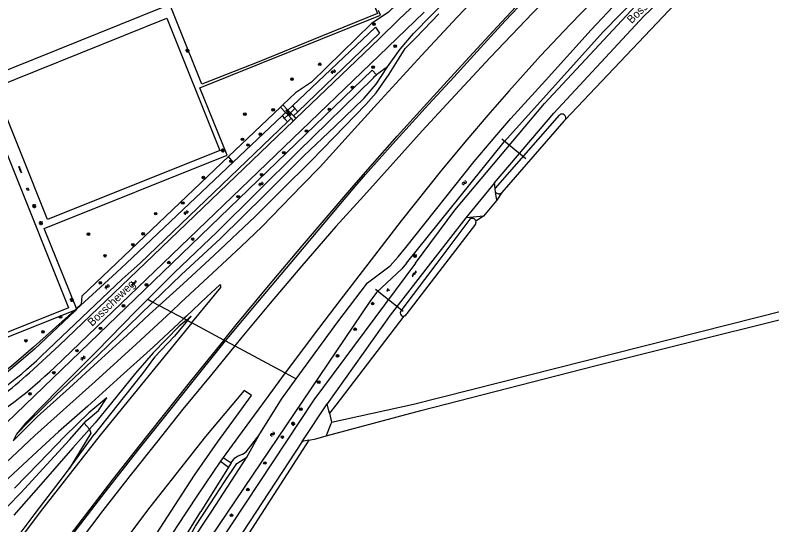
# Model space of a CAD drawing. Extents: x 137999 to 141000, y 397500 to 400501.
# Drawn here: x 138446.7 to 138683.2, y 398918.2 to 399077.5 of the extents above; entities that cross this region are included whole.
import ezdxf

# ---------------------------------------------------------------- set-up
doc = ezdxf.new("R2010")
doc.units = 0
for name, color, linetype in [('gg-afsc-hekwerk', 7, 'Continuous'), ('gg-anno-openbare ruimte label', 7, 'Continuous'), ('gg-knt-BGT kruinlijn', 7, 'Continuous'), ('gg-knt-verharding', 7, 'Continuous'), ('gg-kntw-bovenkant insteek waterloop', 7, 'Continuous'), ('gg-kwrk-duiker nz buis', 7, 'Continuous'), ('gt-grn-groengrens', 7, 'Continuous'), ('gt-symb-boom', 7, 'Continuous'), ('gt-symb-gesloten verharding', 7, 'Continuous'), ('gt-symb-groenvak', 7, 'Continuous'), ('gt-symb-kolk center center', 7, 'Continuous'), ('gt-symb-lichtmast', 7, 'Continuous'), ('gt-symb-tegel verharding', 7, 'Continuous'), ('gt-symb-watersymbool', 7, 'Continuous'), ('gx-grn-maaiveld', 7, 'Continuous')]:
    doc.layers.add(name, color=color, linetype=linetype)

# ---------------------------------------------------------------- blocks, each defined once
blk = doc.blocks.new('gt0-BOOM')
at = {"layer": 'gt-symb-boom'}
for radius in [0.4, 0.2]:
    blk.add_circle((0, 0), radius, dxfattribs=at)
blk = doc.blocks.new('gt0-WA')
at = {"layer": 'gt-symb-watersymbool'}
for centre, start, end in [((-0.32, 0.02), 28.0725, 151.9275), ((0.43, 0.42), 208.0725, 331.9275), ((-0.32, -0.43), 28.0725, 151.9275), ((0.43, -0.03), 208.0725, 331.9275)]:
    blk.add_arc(centre, 0.425, start, end, dxfattribs=at)
blk = doc.blocks.new('gt0-TEG1')
at = {"layer": 'gt-symb-tegel verharding'}
for p, q in [((-1.13, 0), (1.12, 0)), ((-0.9, -0.25), (-0.9, 0.25)), ((-0.45, -0.25), (-0.45, 0.25)), ((0, -0.25), (0, 0.25)), ((0.45, -0.25), (0.45, 0.25)), ((0.9, -0.25), (0.9, 0.25))]:
    blk.add_line(p, q, dxfattribs=at)
blk = doc.blocks.new('gt0-KOLKCC')
at = {"layer": 'gt-symb-kolk center center'}
blk.add_lwpolyline([(-0.38, 0.2), (0.37, 0.2), (0.37, -0.2), (-0.38, -0.2)], close=True, dxfattribs=at)
blk = doc.blocks.new('gt0-LMAST')
at = {"layer": 'gt-symb-lichtmast'}
for p, q in [((-0.18, 0.17), (-0.45, 0.44)), ((0, 0.25), (0, 0.62)), ((0.17, 0.17), (0.44, 0.44)), ((-0.25, 0), (-0.63, 0)), ((-0.18, -0.18), (-0.45, -0.45)), ((0, -0.25), (0, -0.63)), ((0.44, -0.45), (0.17, -0.18)), ((0.25, 0), (0.62, 0))]:
    blk.add_line(p, q, dxfattribs=at)
blk.add_circle((0, 0), 0.25, dxfattribs=at)
blk = doc.blocks.new('gt0-GESVH1')
at = {"layer": 'gt-symb-gesloten verharding'}
for p, q in [((-0.99, -0.26), (0.01, 0.24)), ((0.01, -0.26), (-0.99, 0.24)), ((0.01, 0.24), (1.01, -0.26)), ((1.01, 0.24), (0.01, -0.26))]:
    blk.add_line(p, q, dxfattribs=at)
blk = doc.blocks.new('gt0-GRVAK')
at = {"layer": 'gt-symb-groenvak'}
for p, q in [((-0.11, 0.19), (-0.23, 0.24)), ((-0.18, 0.15), (0.09, 0.15)), ((-0.09, 0.21), (-0.16, 0.32)), ((-0.05, 0.21), (-0.05, 0.39)), ((0, 0.21), (0.06, 0.32)), ((0.02, 0.19), (0.13, 0.24)), ((0.26, -0.05), (0.2, 0.06)), ((0.31, -0.05), (0.31, 0.13)), ((0.35, -0.05), (0.41, 0.06)), ((-0.24, -0.23), (-0.36, -0.18)), ((-0.32, -0.26), (-0.05, -0.26)), ((-0.23, -0.21), (-0.29, -0.09)), ((-0.18, -0.2), (-0.18, -0.02)), ((-0.14, -0.21), (-0.07, -0.09)), ((-0.12, -0.23), (0, -0.18)), ((0.24, -0.07), (0.12, -0.02)), ((0.17, -0.11), (0.44, -0.11)), ((0.37, -0.07), (0.49, -0.02))]:
    blk.add_line(p, q, dxfattribs=at)

msp = doc.modelspace()

# ---------------------------------------------------------------- linework, layer by layer
at = {"layer": 'gg-afsc-hekwerk'}
for p, q in [((138542.24, 399070.77), (138522.87, 399062.86)), ((138530.38, 399049.44), (138529.63, 399048.73)), ((138529.63, 399048.73), (138513.37, 399033.27)), ((138465.86, 398985.77), (138465.36, 398985.32))]:
    msp.add_line(p, q, dxfattribs=at)
for points in [[(138565.97, 399080.94), (138563.3, 399078.28), (138558.06, 399074.85), (138539.36, 399056.53), (138534.35, 399053.22), (138530.38, 399049.44)], [(138513.37, 399033.27), (138467.54, 398989.69), (138467.35, 398987.11), (138465.86, 398985.77)], [(138465.36, 398985.32), (138452.45, 398973.74), (138446.23, 398968.34), (138439.94, 398963.29), (138424.42, 398953.33), (138421.32, 398953.92), (138412.36, 398949.22)]]:
    msp.add_lwpolyline(points, dxfattribs=at)
at = {"layer": 'gg-knt-BGT kruinlijn'}
for p, q in [((138572.03, 399070.45), (138579.08, 399077.9)), ((138568.61, 399067), (138572.03, 399070.45)), ((138566.68, 399063.99), (138568.61, 399067)), ((138563.55, 399059.01), (138566.68, 399063.99)), ((138559.52, 399053.2), (138563.55, 399059.01)), ((138556.35, 399049.55), (138559.52, 399053.2)), ((138546.32, 399039.24), (138556.35, 399049.55)), ((138539.24, 399031.96), (138546.32, 399039.24)), ((138529.89, 399022.69), (138539.24, 399031.96)), ((138521.72, 399014.56), (138529.89, 399022.69)), ((138508.92, 399002.44), (138521.72, 399014.56)), ((138499.23, 398993.49), (138508.92, 399002.44)), ((138491.76, 398986.75), (138499.23, 398993.49)), ((138491.76, 398986.75), (138488.68, 398983.98)), ((138488.68, 398983.98), (138481.69, 398977.42)), ((138500.58, 398982.03), (138501.75, 398983.42)), ((138500.58, 398982.03), (138496.53, 398977.19)), ((138481.69, 398977.42), (138472.57, 398969.11)), ((138496.53, 398977.19), (138490.3, 398970.55)), ((138472.57, 398969.11), (138463.7, 398960.96)), ((138490.3, 398970.55), (138486.52, 398965.5)), ((138486.52, 398965.5), (138480.48, 398957.85)), ((138463.7, 398960.96), (138453.61, 398951.91)), ((138475.4, 398957.91), (138469.78, 398953.21)), ((138480.48, 398957.85), (138471.45, 398946.42)), ((138469.78, 398953.21), (138462.27, 398945.9)), ((138453.61, 398951.91), (138446.11, 398944.49)), ((138462.27, 398945.9), (138454.1, 398937.43)), ((138463.6, 398935.7), (138471.45, 398946.42)), ((138518.96, 398941.02), (138522.83, 398946.08)), ((138517.75, 398940.32), (138518.96, 398941.02)), ((138514.27, 398937.58), (138515.39, 398939.18)), ((138515.39, 398939.18), (138516.37, 398939.76)), ((138516.37, 398939.76), (138517.75, 398940.32)), ((138454.1, 398937.43), (138446.49, 398929.61)), ((138513.35, 398936.26), (138504.8, 398922.39)), ((138514.27, 398937.58), (138513.35, 398936.26)), ((138452.95, 398921.72), (138462.17, 398933.74)), ((138462.17, 398933.74), (138463.6, 398935.7)), ((138497.03, 398909.88), (138504.8, 398922.39)), ((138441.84, 398907.05), (138452.95, 398921.72))]:
    msp.add_line(p, q, dxfattribs=at)
at = {"layer": 'gg-knt-verharding'}
for p, q in [((138571.91, 399081.14), (138566.76, 399076.2)), ((138563.14, 399067.46), (138574.54, 399078.41)), ((138566.76, 399076.2), (138560.42, 399070.11)), ((138560.42, 399070.11), (138534.47, 399045.21)), ((138492.94, 399000), (138563.14, 399067.46)), ((138530.38, 399049.44), (138531.97, 399047.79)), ((138531.22, 399047.08), (138529.63, 399048.73)), ((138533.72, 399044.49), (138532.96, 399045.28)), ((138533.71, 399045.99), (138534.47, 399045.21)), ((138534.47, 399045.21), (138533.72, 399044.49)), ((138533.72, 399044.49), (138487.36, 399000)), ((138459.01, 398967.39), (138492.94, 399000))]:
    msp.add_line(p, q, dxfattribs=at)
for points in [[(138571.8, 399000), (138584.07, 399016.51), (138612.13, 399049.83), (138640.56, 399080.38), (138666.74, 399106.01), (138694.44, 399132.57), (138762.01, 399197.52), (138807.68, 399242.38), (138884.6, 399318.08), (138886.05, 399319.54)], [(138402.84, 399148.3), (138403.65, 399150.21), (138456.18, 399171.33), (138492.8, 399079.87), (138438.9, 399058.2), (138402.84, 399148.3)], [(138505.17, 399163.17), (138522.85, 399170.21), (138559.9, 399077.94), (138542.24, 399070.77)], [(138522.87, 399062.86), (138505.11, 399055.93), (138468.1, 399148.18), (138485.69, 399155.37)], [(138465.86, 398985.77), (138455.8, 399010.82), (138512.98, 399033.73), (138504.48, 399054.79), (138560.86, 399077.5), (138560.3, 399078.91)], [(138463.4, 398985.96), (138409.59, 398964.46), (138372.96, 399055.79), (138426.81, 399077.28), (138463.4, 398985.96)], [(138494.12, 399076.49), (138510.72, 399035.22), (138456.88, 399013.6), (138440.28, 399054.86), (138494.12, 399076.49)], [(138372.18, 399054.35), (138384.62, 399023.2), (138384.22, 399023.01), (138385.77, 399019.21), (138386.17, 399019.33), (138393.94, 398999.98), (138393.5, 398999.78), (138395.03, 398995.96), (138395.5, 398996.11), (138408.93, 398962.81), (138465.36, 398985.32)], [(138532.96, 399045.28), (138532, 399046.27), (138531.22, 399047.08)], [(138531.97, 399047.79), (138532.75, 399046.98), (138533.71, 399045.99)], [(138451.18, 398965.68), (138460.53, 398974.26), (138487.36, 399000)], [(138571.8, 399000), (138540.02, 398957.23), (138505.73, 398905.24), (138460.79, 398836.3)]]:
    msp.add_lwpolyline(points, dxfattribs=at)
for centre, radius, start, end in [((138361.13, 399069.27), 141.28, 300.7543, 313.8524), ((138374.59, 399049.23), 113.34, 300.9525, 312.5092)]:
    msp.add_arc(centre, radius, start, end, dxfattribs=at)
at = {"layer": 'gg-kntw-bovenkant insteek waterloop'}
for p, q in [((138533.39, 399049.15), (138559.37, 399073.72)), ((138559.37, 399073.72), (138560.62, 399071.84)), ((138560.62, 399071.84), (138535.02, 399047.25)), ((138558.3, 399060.28), (138495.8, 399000)), ((138559.68, 399058.83), (138558.3, 399060.28)), ((138514.84, 399031.57), (138530.13, 399046.04)), ((138531.81, 399044.17), (138485.81, 399000)), ((138481.48, 399000), (138514.84, 399031.57)), ((138495.8, 399000), (138426, 398932.69))]:
    msp.add_line(p, q, dxfattribs=at)
for points in [[(138569.06, 399000), (138599.49, 399037.92), (138630.55, 399072.31), (138666.53, 399109.13), (138692.73, 399135.04), (138766.57, 399206.06), (138805.76, 399244.25), (138841.1, 399278.43), (138881.4, 399317.3), (138882.07, 399318.34)], [(138509.81, 399009.73), (138535.1, 399034.73), (138558.73, 399057.84), (138559.11, 399058.41), (138559.68, 399058.83)], [(138533.39, 399049.15), (138534.13, 399048.29), (138535.02, 399047.25)], [(138530.13, 399046.04), (138530.88, 399045.21), (138531.81, 399044.17)], [(138485.81, 399000), (138480.16, 398994.97), (138454.86, 398970.88)], [(138569.06, 399000), (138567.59, 398998.16), (138559.63, 398990.84), (138557.55, 398988.03), (138505.1, 398910.32), (138485.15, 398878.9), (138465.82, 398849.17), (138462.27, 398851.67)], [(138481.48, 399000), (138478.37, 398997.01), (138465.94, 398985.55)], [(138465.94, 398985.55), (138465.44, 398985.1), (138452.79, 398973.05), (138440.44, 398962.67), (138427.05, 398954), (138415.33, 398947.39)]]:
    msp.add_lwpolyline(points, dxfattribs=at)
msp.add_arc((138363.58, 399066.74), 132.37, 299.4603, 313.5986, dxfattribs=at)
at = {"layer": 'gg-kwrk-duiker nz buis'}
for p, q in [((138606.26, 399032.56), (138598.75, 399038.69)), ((138559.37, 398991.87), (138567.95, 398984.92))]:
    msp.add_line(p, q, dxfattribs=at)
msp.add_lwpolyline([(138530.73, 399045.07), (138532, 399046.27), (138532.75, 399046.98), (138534.13, 399048.29), (138534.14, 399048.3)], dxfattribs=at)
at = {"layer": 'gt-grn-groengrens'}
for p, q in [((138530.13, 399046.04), (138531.22, 399047.08)), ((138531.97, 399047.79), (138533.39, 399049.15)), ((138535.02, 399047.25), (138533.71, 399045.99)), ((138532.96, 399045.28), (138531.81, 399044.17)), ((138514.84, 399031.57), (138513.37, 399033.27))]:
    msp.add_line(p, q, dxfattribs=at)
at = {"layer": 'gx-grn-maaiveld'}
for p, q in [((138655.21, 399083.4), (138618.61, 399044.8)), ((138563.06, 399061.32), (138559.68, 399058.83)), ((138618.15, 399044.36), (138598.76, 399022.05)), ((138596.49, 399025.09), (138587.57, 399014.09)), ((138596.73, 399023.22), (138596.49, 399025.09)), ((138596.86, 399022.19), (138596.73, 399023.22)), ((138597.19, 399019.63), (138596.86, 399022.19)), ((138598.76, 399022.05), (138597.19, 399019.63)), ((138597.19, 399019.63), (138593.04, 399014.62)), ((138587.57, 399014.09), (138576.56, 399000)), ((138593.04, 399014.62), (138590.68, 399013.13)), ((138488.16, 398988.68), (138489.78, 398987.81)), ((138489.78, 398987.81), (138491.76, 398986.75)), ((138491.76, 398986.75), (138495.45, 398984.77)), ((138495.45, 398984.77), (138499.41, 398982.66)), ((138500.27, 398982.19), (138501.75, 398983.42)), ((138568.54, 398983.5), (138568.21, 398983.4)), ((138500.27, 398982.19), (138499.41, 398982.66)), ((138500.27, 398982.19), (138500.58, 398982.03)), ((138500.58, 398982.03), (138501.93, 398981.31)), ((138511.96, 398975.93), (138501.93, 398981.31)), ((138512.45, 398975.67), (138511.96, 398975.93)), ((138512.45, 398975.67), (138515.33, 398974.12)), ((138515.33, 398974.12), (138531.08, 398965.68)), ((138531.08, 398965.68), (138534.59, 398963.8)), ((138536.45, 398944.23), (138544.24, 398956.06)), ((138544.96, 398953.07), (138545.63, 398950.3)), ((138468.32, 398949.96), (138469.96, 398948.07)), ((138447.17, 398946.55), (138446.11, 398944.49)), ((138519.12, 398939.39), (138522.83, 398946.08)), ((138511.71, 398939.22), (138510.93, 398938.07)), ((138511.71, 398939.22), (138514.27, 398937.58)), ((138510.93, 398938.07), (138513.35, 398936.26))]:
    msp.add_line(p, q, dxfattribs=at)
for points in [[(138782.72, 399248.98), (138780.45, 399246.78), (138754.03, 399221.18), (138729.59, 399197.44), (138715.3, 399183.49), (138703.21, 399172.02), (138691.93, 399161.06), (138680.32, 399149.78), (138667.89, 399137.77), (138653.22, 399123.39), (138641.49, 399111.83), (138629.42, 399099.73), (138619, 399089.09), (138608.45, 399078.21), (138595.11, 399064.19), (138584.24, 399052.51), (138573.94, 399041.33), (138564.83, 399031.26), (138555.63, 399021.02), (138546.98, 399011.39), (138536.29, 398999.15), (138526.38, 398987.5), (138517.55, 398976.85), (138515.33, 398974.12)], [(138563.93, 398999.16), (138566.36, 399001.99), (138568.83, 399004.91), (138590.2, 399031.73), (138597.25, 399040.05), (138601.66, 399045.12), (138612.41, 399057.05), (138626.74, 399072.88), (138635.18, 399081.84), (138639.93, 399086.79), (138652.44, 399099.34), (138665.21, 399112.5), (138682.74, 399130.2), (138695.72, 399142.58), (138708.72, 399155.24), (138724.56, 399170.64), (138740.53, 399185.68), (138760.84, 399205.22)], [(138703.72, 399157.61), (138673.36, 399128.03), (138651.73, 399106.8), (138638.1, 399093.03), (138620.18, 399074.56), (138610.88, 399064.72), (138600.97, 399053.71), (138594.4, 399046.24), (138587.84, 399038.5), (138579.97, 399029.04), (138567.33, 399013.21), (138559.01, 399002.34), (138548.19, 398988.32), (138539.9, 398977.4), (138531.5, 398966.26), (138531.08, 398965.68)], [(138511.96, 398975.93), (138515.83, 398980.7), (138525.39, 398992.27), (138536.52, 399005.52), (138551.89, 399023.52), (138558.42, 399030.91), (138566.13, 399039.6), (138574.37, 399048.73), (138581.76, 399056.83), (138589.86, 399065.69), (138597.36, 399073.85), (138604.67, 399081.63), (138612.45, 399089.8), (138620.3, 399098), (138628.01, 399105.89), (138635.47, 399113.55), (138643.22, 399121.37), (138650.06, 399128.09), (138656.84, 399134.77), (138666.44, 399144.15)], [(138512.45, 398975.67), (138513.49, 398976.96), (138522.56, 398987.83), (138534.29, 399001.78), (138543.64, 399012.81), (138552.38, 399023.19), (138556.22, 399027.66), (138564.79, 399037.25), (138575.85, 399049.57), (138583.75, 399058.11), (138592.12, 399067.28), (138599.86, 399075.68), (138607.86, 399084.24), (138616.3, 399093.11), (138623, 399100), (138631.24, 399108.46), (138640.11, 399117.39), (138648.97, 399126.19), (138658.18, 399135.3), (138666.77, 399143.83), (138666.44, 399144.15)], [(138563.06, 399061.32), (138567.07, 399066.81), (138571.24, 399071.68), (138576.83, 399077.45), (138587.43, 399087.94), (138594.22, 399094.8)], [(138593.78, 399086.27), (138584.85, 399076.88), (138573.72, 399064.86), (138559.96, 399049.83), (138550.83, 399039.79), (138542.01, 399030.11), (138536.46, 399024.37), (138530.1, 399017.74), (138523.83, 399011.36), (138517.31, 399005.18), (138508.44, 398996.81), (138498.54, 398987.64), (138495.45, 398984.77)], [(138596.49, 399025.09), (138615.03, 399046.87), (138643.18, 399077.18), (138649.62, 399083.44)], [(138489.78, 398987.81), (138498.57, 398996.34), (138510.85, 399007.64), (138524.75, 399021.36), (138536.96, 399033.48), (138546.58, 399042.65), (138555.79, 399051.56), (138559.52, 399055.89), (138563.06, 399061.32)], [(138545.63, 398950.3), (138571.2, 398955.95), (138803.01, 399014.58), (138989.71, 399060.11)], [(138543.94, 398945.98), (138573.48, 398953.97), (138627.83, 398967.89), (138803.03, 399011.67), (138908.84, 399037.73), (138968.12, 399051.52), (138989.44, 399057.29)], [(138596.73, 399023.22), (138596.83, 399023.44), (138616.79, 399046.24)], [(138593.04, 399014.62), (138588.76, 399014.21), (138587.57, 399014.09)], [(138588.84, 399013.74), (138578.49, 399000), (138567.29, 398985.11)], [(138590.52, 399012.13), (138581.21, 399000), (138569.1, 398984.21), (138569.08, 398984.16), (138569.07, 398984.11), (138569.05, 398984.07), (138569.04, 398984.02)], [(138488.16, 398988.68), (138496.39, 398996.99), (138509.81, 399009.73)], [(138576.56, 399000), (138563.86, 398983.76), (138544.24, 398956.06)], [(138534.59, 398963.8), (138547.52, 398981.64), (138556.85, 398993.82), (138563.93, 398999.16)], [(138501.93, 398981.31), (138502.2, 398981.64), (138511.02, 398992.39), (138511.03, 398992.99), (138510.74, 398993.19), (138506.66, 398989.46), (138500.26, 398983.44), (138499.41, 398982.66)], [(138488.16, 398988.68), (138484.38, 398984.88), (138472.29, 398972.49), (138460.67, 398960.91), (138450.01, 398949.98), (138447.17, 398946.55)], [(138447.17, 398946.55), (138451.16, 398950.56), (138459.55, 398958.82), (138472.72, 398971.23), (138485.55, 398983.72), (138489.78, 398987.81)], [(138334.53, 398832.59), (138347.74, 398845.28), (138366.67, 398863.62), (138387.38, 398883.59), (138411.49, 398906.85), (138423.77, 398918.74), (138452.89, 398946.11), (138471.75, 398963.02), (138484.51, 398974.61), (138495.45, 398984.77)], [(138568.21, 398983.4), (138546.96, 398955.61), (138544.96, 398953.07)], [(138499.41, 398982.66), (138489.92, 398973.85), (138478.64, 398963.66), (138469.4, 398955.25), (138460.33, 398947.22), (138453.63, 398941.07), (138444.67, 398932.82), (138432.98, 398921.77), (138417.26, 398906.59), (138399.64, 398889.59), (138385.05, 398875.64), (138367.17, 398858.32), (138349.33, 398841.16), (138333.87, 398826.24), (138316.88, 398810.07), (138304.82, 398798.46), (138292.22, 398786.3), (138279.23, 398773.8), (138267.43, 398762.44), (138257.96, 398753.35), (138247.34, 398743.36), (138238.39, 398734.96), (138228.54, 398725.85), (138219.7, 398717.86)], [(138501.93, 398981.31), (138473.35, 398946.25), (138454.53, 398922.28), (138436.97, 398898.82), (138420.73, 398876.2), (138406.46, 398855.7), (138389.11, 398830.38), (138374.16, 398808.03), (138357.61, 398782.41), (138337.09, 398749.31), (138322.84, 398725.57), (138306.14, 398696.86), (138294.74, 398676.9)], [(138500.27, 398982.19), (138497.94, 398980.27), (138489.87, 398971.99), (138484.35, 398965.57), (138476.89, 398956.34), (138471.75, 398950.1), (138469.96, 398948.07)], [(138511.96, 398975.93), (138501.93, 398963.57), (138488.51, 398946.76), (138477.26, 398932.48), (138465.23, 398916.8), (138454.1, 398902.02), (138442.39, 398886.25), (138431.73, 398871.47), (138423.79, 398860.21), (138409, 398839.04), (138400.22, 398826.26), (138391.06, 398812.74), (138383.32, 398801.2), (138369.25, 398779.46), (138351.53, 398751.27), (138335.99, 398725.63), (138320.07, 398698.46), (138305.76, 398673.14), (138304.77, 398671.25)], [(138305.51, 398670.84), (138318.83, 398694.74), (138335.5, 398723.24), (138353.01, 398752.39), (138371.79, 398782.1), (138383.87, 398800.92), (138391.62, 398812.28), (138401.25, 398826.65), (138409.13, 398838.16), (138419.71, 398853.23), (138427.79, 398864.74), (138439.06, 398880.6), (138447.18, 398891.55), (138456.66, 398904.44), (138465.19, 398915.76), (138474.86, 398928.37), (138485.07, 398941.42), (138495.05, 398953.91), (138502.76, 398963.65), (138512.45, 398975.67)], [(138515.33, 398974.12), (138508.14, 398965.28), (138499.1, 398954.3), (138490.91, 398943.97), (138482.68, 398933.64), (138474.18, 398922.64), (138466.42, 398912.51), (138457.95, 398901.32), (138448.31, 398888.42), (138439.64, 398876.56), (138431.08, 398864.56), (138422.11, 398851.79), (138414.01, 398840.2), (138403.68, 398825.33), (138393.35, 398810.12), (138386.42, 398799.63), (138373.52, 398779.54), (138349.79, 398741.53), (138323.85, 398697.93), (138308.01, 398669.51)], [(138531.08, 398965.68), (138524.01, 398956.01), (138516.48, 398945.84), (138511.71, 398939.22)], [(138522.83, 398946.08), (138529.99, 398957.46), (138534.59, 398963.8)], [(138445.2, 398838.89), (138454.46, 398854.65), (138459.76, 398863.94), (138465.34, 398873.45), (138471.5, 398883.92), (138477.49, 398893.83), (138483.55, 398903.63), (138489.79, 398913.61), (138496.63, 398924.24), (138502.81, 398933.7), (138510, 398944), (138515.54, 398951.76), (138520.63, 398958.64), (138518.24, 398960.23), (138506.25, 398945.82), (138488.86, 398923.75), (138469.91, 398898.56), (138451.9, 398873.72), (138435.15, 398850.39)], [(138468.32, 398949.96), (138468.95, 398950.67), (138472.74, 398953.91), (138475.4, 398957.91)], [(138544.96, 398953.07), (138544.69, 398954.21), (138544.24, 398956.06)], [(138543.94, 398945.98), (138544.13, 398946.45), (138545.5, 398949.91), (138545.64, 398950.25), (138545.63, 398950.3)], [(138444.35, 398923.94), (138448.63, 398928.31), (138454.26, 398934.47), (138459.05, 398939.64), (138463.69, 398944.8), (138468.32, 398949.96)], [(138469.96, 398948.07), (138464.81, 398942.28), (138454.81, 398930.85), (138446.37, 398921.18)], [(138469.96, 398948.07), (138470.42, 398946.86), (138463.6, 398935.7)], [(138538.48, 398944.62), (138540.71, 398945.04), (138543.94, 398945.98)], [(138536.45, 398944.23), (138509.39, 398903.14), (138463.79, 398832.99)], [(138538.48, 398944.62), (138500.76, 398886.17), (138474.86, 398846.97), (138470.28, 398839.08)], [(138538.48, 398944.62), (138538.47, 398944.61), (138536.45, 398944.23)], [(138493.8, 398900.86), (138496.8, 398906.75), (138503.12, 398917.76), (138509.47, 398927.48), (138512.14, 398931.65), (138515.98, 398937.39), (138519.12, 398939.39)], [(138493.8, 398900.86), (138508.22, 398922.45), (138519.12, 398939.39)], [(138510.93, 398938.07), (138503.76, 398927.52), (138497.3, 398917.73), (138491.67, 398908.92), (138485.99, 398899.71), (138478.97, 398888.11), (138471.93, 398876.34), (138464.28, 398863.27), (138454.82, 398847.09), (138445.4, 398830.65), (138437.66, 398816.93), (138433.16, 398808.86)]]:
    msp.add_lwpolyline(points, dxfattribs=at)
for centre, radius, start, end in [((138617.6, 399045.4), 1.17, 329.4371, 134.0174), ((138617.6, 399045.39), 1.16, 297.7017, 329.5039), ((138597.87, 399022.84), 1.2, 212.82, 318.401), ((138589.55, 399012.79), 1.18, 16.4863, 126.8494), ((138589.55, 399012.79), 1.18, 325.7938, 16.5674), ((138568.08, 398984.43), 1.04, 139.4793, 222.2656), ((138568.08, 398984.43), 1.04, 222.1871, 277.2867), ((138568.08, 398984.43), 1.04, 296.1552, 336.8804)]:
    msp.add_arc(centre, radius, start, end, dxfattribs=at)

# ---------------------------------------------------------------- block references
at = {"layer": 'gt-symb-boom'}
for p in [(138558.86, 399074.64), (138565.5, 399067.79), (138541.91, 399062.12), (138558.57, 399061.23), (138533.23, 399057.46), (138552.13, 399054.91), (138527.34, 399047.9), (138544.89, 399048.04), (138518.48, 399046.54), (138523.33, 399040.26), (138537.78, 399041.26), (138517.79, 399038.65), (138519.49, 399036.9), (138530.68, 399034.48), (138514.15, 399031.77), (138505.55, 399026.74), (138523.74, 399027.6), (138516.4, 399020.74), (138499.13, 399018.75), (138490.64, 399015.45), (138469.62, 399009.03), (138486.71, 399009.15), (138502.21, 399007.5), (138483.53, 399005.72), (138474.82, 399002.29), (138494.74, 399000.14), (138473.34, 398993.82), (138487.78, 398993.2), (138480.59, 398986.63), (138558.43, 398987.34), (138460.94, 398983.17), (138455.44, 398978.51), (138473.4, 398979.62), (138552.98, 398979.32), (138450.11, 398975.73), (138466.05, 398972.64), (138547.48, 398970.99), (138458.81, 398965.73), (138541.59, 398962.77), (138451.38, 398959.12), (138536.01, 398954.36), (138530.22, 398945.62), (138524.78, 398937.54), (138519.43, 398929.21), (138514.34, 398921.2)]:
    msp.add_blockref('gt0-BOOM', p, dxfattribs=at)
at = {"layer": 'gt-symb-gesloten verharding'}
for p, rotation in [((138571.43, 398996.66), 51.984339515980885), ((138483.85, 398993.7), -136.13442163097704)]:
    msp.add_blockref('gt0-GESVH1', p, dxfattribs=dict(at, rotation=rotation))
at = {"layer": 'gt-symb-groenvak'}
msp.add_blockref('gt0-GRVAK', (138563.23, 398991.61), dxfattribs=at)
at = {"layer": 'gt-symb-kolk center center', "rotation": 111.71629047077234}
msp.add_blockref('gt0-KOLKCC', (138450.64, 399023.07), dxfattribs=at)
at = {"layer": 'gt-symb-lichtmast'}
for p in [(138500.59, 399066.39), (138511.63, 399035.17), (138452.72, 399017.81), (138454.8, 399012.51), (138571.66, 399002.24), (138464.46, 398988.48), (138533.59, 398949.81)]:
    msp.add_blockref('gt0-LMAST', p, dxfattribs=at)
at = {"layer": 'gt-symb-tegel verharding'}
for p, rotation in [((138532.08, 399046.96), -46.29643001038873), ((138448.26, 399029.16), 111.53536487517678)]:
    msp.add_blockref('gt0-TEG1', p, dxfattribs=dict(at, rotation=rotation))
at = {"layer": 'gt-symb-watersymbool'}
for p, rotation in [((138546.12, 399059.76), 43.86557836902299), ((138587.07, 399025.01), 51.984339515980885), ((138523.49, 399024.68), 44.43273358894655), ((138500.12, 399015.72), 54.27586519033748), ((138475.48, 398992.59), 54.27586519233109), ((138467.9, 398970.25), 54.27586519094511), ((138527.13, 398946.5), 56.087487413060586)]:
    msp.add_blockref('gt0-WA', p, dxfattribs=dict(at, rotation=rotation))

# ---------------------------------------------------------------- texts
at = {"layer": 'gg-anno-openbare ruimte label'}
for rotation, p in [(44.4, (138639.34, 399074.68)), (43.9, (138470.82, 398980.06))]:
    msp.add_text('Bosscheweg', height=2.5, rotation=rotation, dxfattribs=at).set_placement(p)

doc.saveas('drawing.dxf')
